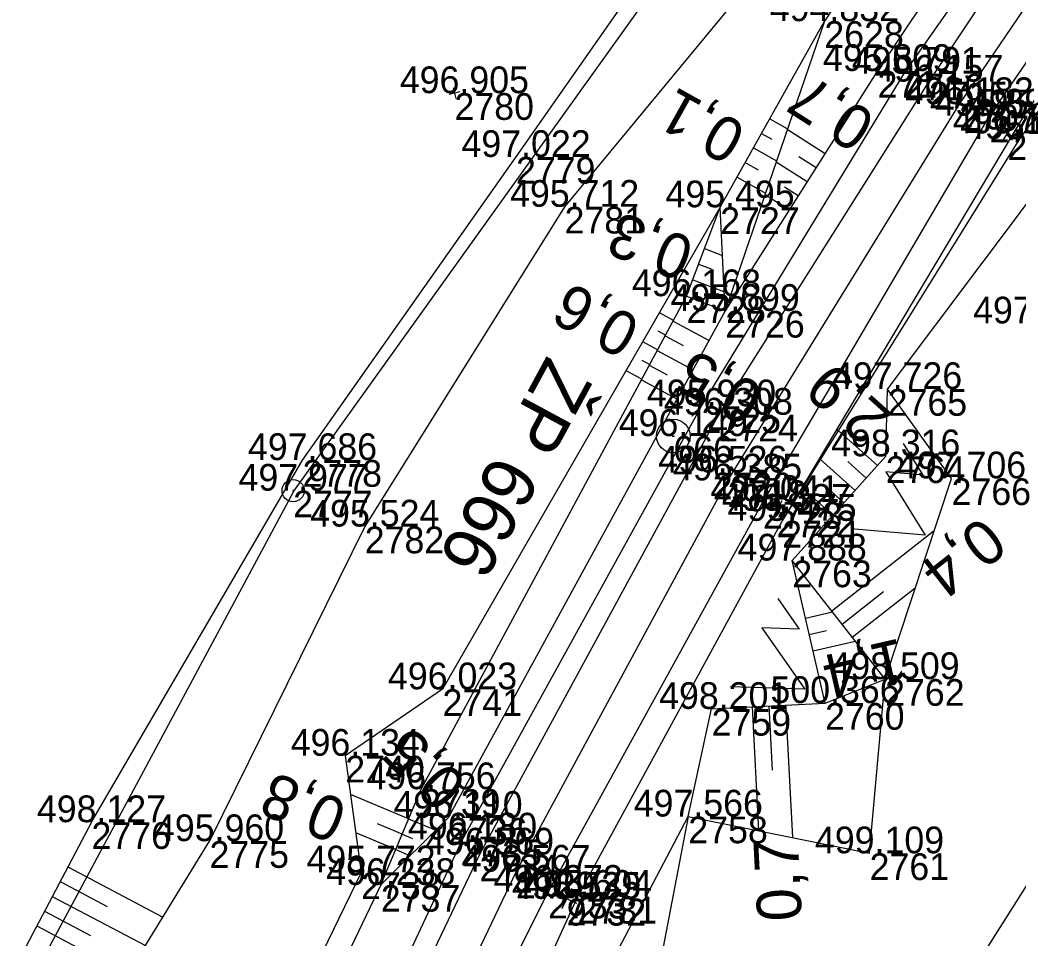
# Model space of a CAD drawing. Extents: x -1234191 to 23050, y -1290331 to -741191.
# Drawn here: x -864868.02 to -864823.18, y -1103072.61 to -1103031.37 of the extents above; entities that cross this region are included whole.
import ezdxf

# ---------------------------------------------------------------- set-up
doc = ezdxf.new("R2010")
doc.units = 0
for name, color, linetype in [('Vrstva 1', 7, 'Continuous'), ('Vrstva 4', 7, 'Continuous'), ('Vrstva 48', 7, 'Continuous'), ('Vrstva 49', 7, 'Continuous'), ('Vrstva 50', 7, 'Continuous'), ('Vrstva 53', 7, 'Continuous'), ('Vrstva 60', 7, 'Continuous'), ('Vrstva 61', 7, 'Continuous'), ('Vrstva 63', 7, 'Continuous'), ('Vrstva 7', 7, 'Continuous')]:
    doc.layers.add(name, color=color, linetype=linetype)

msp = doc.modelspace()

# ---------------------------------------------------------------- linework, layer by layer
at = {"layer": 'Vrstva 1'}
msp.add_lwpolyline([(-864787.36, -1102983.609), (-864800.066, -1102999.573), (-864808.926, -1103011.127), (-864817.494, -1103022.893), (-864825.83, -1103035.148), (-864836.227, -1103052.052), (-864845.733, -1103069.628), (-864853.5, -1103085.902), (-864861.945, -1103106.356), (-864868.475, -1103125.08), (-864874.102, -1103144.427), (-864878.675, -1103163.914), (-864882.14, -1103183.501), (-864883.755, -1103195.656), (-864884.979, -1103207.79), (-864886.147, -1103227.601), (-864886.275, -1103247.702), (-864885.251, -1103267.649), (-864883.95, -1103281.168), (-864883.144, -1103287.68), (-864880.026, -1103307.256), (-864876.201, -1103325.274)], dxfattribs=at)
at = {"layer": 'Vrstva 4'}
for points in [[(-864855.92, -1103084.82), (-864848.135, -1103068.183), (-864837.4, -1103048.723), (-864828.294, -1103033.779), (-864819.737, -1103021.567)], [(-864819.071, -1103021.913), (-864827.188, -1103034.138), (-864836.641, -1103049.101), (-864847.372, -1103068.859), (-864855.216, -1103085.296)], [(-864816.381, -1103023.935), (-864824.465, -1103035.662), (-864834.642, -1103053.018), (-864844.293, -1103070.531), (-864852.293, -1103086.512)], [(-864815.579, -1103024.784), (-864822.94, -1103035.693), (-864833.777, -1103053.868)], [(-864833.777, -1103053.868), (-864842.968, -1103070.758), (-864850.48, -1103087.221)]]:
    msp.add_lwpolyline(points, dxfattribs=at)
at = {"layer": 'Vrstva 48'}
for p, q in [((-864834.337, -1103035.808), (-864833.535, -1103036.256)), ((-864834.703, -1103036.462), (-864834.242, -1103036.72)), ((-864831.849, -1103037.375), (-864833.549, -1103036.296)), ((-864835.069, -1103037.117), (-864834.028, -1103037.699)), ((-864835.435, -1103037.771), (-864834.855, -1103038.096)), ((-864832.653, -1103038.641), (-864834.048, -1103037.756)), ((-864832.251, -1103038.008), (-864833.025, -1103037.517)), ((-864835.802, -1103038.426), (-864834.522, -1103039.142)), ((-864833.457, -1103039.908), (-864834.547, -1103039.216)), ((-864833.055, -1103039.274), (-864833.676, -1103038.88)), ((-864837.265, -1103041.638), (-864836.455, -1103041.945)), ((-864837.531, -1103042.339), (-864836.973, -1103042.551)), ((-864837.797, -1103043.04), (-864836.374, -1103043.58)), ((-864838.663, -1103044.866), (-864839.293, -1103044.527)), ((-864838.679, -1103044.897), (-864837.06, -1103045.768)), ((-864839.018, -1103045.526), (-864839.343, -1103045.352)), ((-864839.374, -1103046.187), (-864840.042, -1103045.827)), ((-864839.035, -1103045.557), (-864838.227, -1103045.992)), ((-864839.39, -1103046.218), (-864837.78, -1103047.085)), ((-864839.729, -1103046.847), (-864840.073, -1103046.662)), ((-864840.085, -1103047.508), (-864840.791, -1103047.127)), ((-864839.746, -1103046.878), (-864838.943, -1103047.31)), ((-864840.101, -1103047.538), (-864838.499, -1103048.401)), ((-864831.332, -1103049.768), (-864831.257, -1103049.813)), ((-864829.5, -1103051.388), (-864831.257, -1103049.813)), ((-864831.716, -1103050.412), (-864831.685, -1103050.431)), ((-864832.1, -1103051.056), (-864832.049, -1103051.087)), ((-864830.502, -1103052.505), (-864832.061, -1103051.107)), ((-864830.001, -1103051.946), (-864830.83, -1103051.203)), ((-864832.485, -1103051.7), (-864832.465, -1103051.712)), ((-864832.869, -1103052.345), (-864832.841, -1103052.361)), ((-864831.503, -1103053.621), (-864832.865, -1103052.4)), ((-864831.002, -1103053.063), (-864831.733, -1103052.408)), ((-864831.551, -1103057.914), (-864826.945, -1103054.307)), ((-864831.088, -1103058.505), (-864829.229, -1103057.049)), ((-864830.626, -1103059.095), (-864827.796, -1103056.879)), ((-864832.727, -1103058.242), (-864831.512, -1103057.963)), ((-864832.559, -1103058.973), (-864831.78, -1103058.794)), ((-864832.391, -1103059.704), (-864830.491, -1103059.267)), ((-864835.127, -1103062.223), (-864834.838, -1103067.791)), ((-864834.378, -1103062.184), (-864834.229, -1103065.065)), ((-864833.629, -1103062.146), (-864833.32, -1103068.099)), ((-864850.556, -1103067.255), (-864853.167, -1103066.158)), ((-864850.847, -1103067.946), (-864851.949, -1103067.483)), ((-864850.556, -1103067.255), (-864849.34, -1103067.765)), ((-864851.137, -1103068.638), (-864852.934, -1103067.883)), ((-864850.847, -1103067.946), (-864850.38, -1103068.142)), ((-864851.137, -1103068.638), (-864850.487, -1103068.911)), ((-864865.862, -1103069.41), (-864861.592, -1103071.666)), ((-864866.213, -1103070.074), (-864864.099, -1103071.19)), ((-864866.563, -1103070.737), (-864862.378, -1103072.947)), ((-864866.913, -1103071.4), (-864864.842, -1103072.494)), ((-864867.263, -1103072.063), (-864863.164, -1103074.229))]:
    msp.add_line(p, q, dxfattribs=at)
at = {"layer": 'Vrstva 49'}
for p, q in [((-864848.253, -1103034.598), (-864848.739, -1103034.714)), ((-864848.554, -1103034.413), (-864848.438, -1103034.899))]:
    msp.add_line(p, q, dxfattribs=at)
for points in [[(-864864.803, -1103067.405), (-864855.322, -1103051.138), (-864845.733, -1103037.523), (-864837.273, -1103025.418), (-864823.376, -1103006.596), (-864814.148, -1102994.673), (-864803.644, -1102992.309)], [(-864803.644, -1102992.309), (-864809.056, -1102996.882), (-864818.261, -1103010.716), (-864831.882, -1103031.421)], [(-864809.056, -1102996.882), (-864811.483, -1102996.245), (-864820.166, -1103008.494), (-864834.793, -1103029.157), (-864843.552, -1103039.76), (-864852.527, -1103054.125)], [(-864806.279, -1103012.707), (-864815.579, -1103024.784), (-864822.94, -1103035.693), (-864833.777, -1103053.868)], [(-864805.429, -1103013.211), (-864814.601, -1103024.977), (-864823.116, -1103036.714), (-864833.777, -1103053.868)], [(-864821.024, -1103020.98), (-864829.491, -1103033.659)], [(-864836.332, -1103044.437), (-864836.561, -1103039.783), (-864831.882, -1103031.421)], [(-864831.882, -1103031.421), (-864836.332, -1103044.437)], [(-864829.491, -1103033.659), (-864836.332, -1103044.437)], [(-864836.946, -1103062.318), (-864831.851, -1103062.053), (-864833.323, -1103055.651), (-864829.124, -1103050.968), (-864829.039, -1103047.948), (-864820.401, -1103036.45)], [(-864836.561, -1103039.783), (-864849.033, -1103061.436), (-864853.401, -1103064.421), (-864852.694, -1103069.662), (-864859.407, -1103083.519)], [(-864851.805, -1103070.227), (-864849.997, -1103065.923), (-864838.076, -1103043.776), (-864836.561, -1103039.783)], [(-864838.076, -1103043.776), (-864836.332, -1103044.437)], [(-864836.332, -1103044.437), (-864848.786, -1103067.212), (-864851.805, -1103070.227)], [(-864829.153, -1103060.976), (-864826.167, -1103051.959), (-864829.039, -1103047.948)], [(-864811.071, -1103051.708), (-864834.967, -1103089.456)], [(-864833.777, -1103053.868), (-864842.968, -1103070.758), (-864850.48, -1103087.221)], [(-864852.527, -1103054.125), (-864859.5, -1103068.257)], [(-864831.851, -1103062.053), (-864829.153, -1103060.976), (-864833.323, -1103055.651)], [(-864837.993, -1103067.151), (-864829.85, -1103068.803), (-864829.153, -1103060.976)], [(-864848.041, -1103086.285), (-864837.993, -1103067.151), (-864836.946, -1103062.318)], [(-864864.803, -1103067.405), (-864871.589, -1103080.252), (-864877.953, -1103100.004), (-864884.278, -1103123.532), (-864887.37, -1103144.597)], [(-864837.993, -1103067.151), (-864842.054, -1103088.354), (-864834.967, -1103089.456)], [(-864881.577, -1103125.033), (-864874.894, -1103104.785), (-864868.756, -1103083.343), (-864859.5, -1103068.257)], [(-864851.805, -1103070.227), (-864858.462, -1103084.152)]]:
    msp.add_lwpolyline(points, dxfattribs=at)
at = {"layer": 'Vrstva 50'}
for points in [[(-864828.338, -1103050.391), (-864827.453, -1103051.816), (-864829.124, -1103051.669), (-864827.355, -1103054.518), (-864830.696, -1103054.224)], [(-864833.977, -1103057.363), (-864833.015, -1103058.736), (-864834.691, -1103058.682), (-864832.766, -1103061.429), (-864836.118, -1103061.321)]]:
    msp.add_lwpolyline(points, dxfattribs=at)
at = {"layer": 'Vrstva 53'}
msp.add_line((-864855.72, -1103052.469), (-864855.768, -1103052.557), dxfattribs=at)
msp.add_lwpolyline([(-864889.03, -1103323.28), (-864892.77, -1103263.78), (-864892.91, -1103184.37), (-864883.42, -1103119.48), (-864874.29, -1103087.16), (-864855.71, -1103052.53), (-864814.57, -1102995.09), (-864799.32, -1102988.77), (-864779.65, -1102957.8), (-864778.43, -1102951.42), (-864757.64, -1102926.36), (-864755.77, -1102924.22), (-864753.95, -1102921.47), (-864728.77, -1102872.58), (-864694.07, -1102830.31)], dxfattribs=at)
msp.add_circle((-864855.744, -1103052.513), 0.499, dxfattribs=at)
at = {"layer": 'Vrstva 60'}
for p, q in [((-864831.882, -1103031.421), (-864831.882, -1103031.421)), ((-864829.491, -1103033.659), (-864829.491, -1103033.659)), ((-864828.294, -1103033.779), (-864828.294, -1103033.779)), ((-864827.188, -1103034.138), (-864827.188, -1103034.138)), ((-864848.496, -1103034.656), (-864848.496, -1103034.656)), ((-864825.83, -1103035.148), (-864825.83, -1103035.148)), ((-864824.465, -1103035.662), (-864824.465, -1103035.662)), ((-864823.661, -1103036.461), (-864823.661, -1103036.461)), ((-864845.733, -1103037.523), (-864845.733, -1103037.523)), ((-864843.552, -1103039.76), (-864843.552, -1103039.76)), ((-864836.561, -1103039.783), (-864836.561, -1103039.783)), ((-864838.076, -1103043.776), (-864838.076, -1103043.776)), ((-864836.332, -1103044.437), (-864836.332, -1103044.437)), ((-864829.039, -1103047.948), (-864829.039, -1103047.948)), ((-864837.4, -1103048.723), (-864837.4, -1103048.723)), ((-864836.641, -1103049.101), (-864836.641, -1103049.101)), ((-864838.665, -1103050.059), (-864838.665, -1103050.059)), ((-864855.322, -1103051.138), (-864855.322, -1103051.138)), ((-864829.124, -1103050.968), (-864829.124, -1103050.968)), ((-864836.895, -1103051.7), (-864836.895, -1103051.7)), ((-864836.227, -1103052.052), (-864836.227, -1103052.052)), ((-864826.167, -1103051.959), (-864826.167, -1103051.959)), ((-864855.744, -1103052.513), (-864855.744, -1103052.513)), ((-864834.642, -1103053.018), (-864834.642, -1103053.018)), ((-864834.035, -1103053.414), (-864834.035, -1103053.414)), ((-864833.777, -1103053.868), (-864833.777, -1103053.868)), ((-864852.527, -1103054.125), (-864852.527, -1103054.125)), ((-864833.323, -1103055.651), (-864833.323, -1103055.651)), ((-864829.153, -1103060.976), (-864829.153, -1103060.976)), ((-864849.033, -1103061.436), (-864849.033, -1103061.436)), ((-864831.851, -1103062.053), (-864831.851, -1103062.053)), ((-864836.946, -1103062.318), (-864836.946, -1103062.318)), ((-864853.401, -1103064.421), (-864853.401, -1103064.421)), ((-864849.997, -1103065.923), (-864849.997, -1103065.923)), ((-864864.803, -1103067.405), (-864864.803, -1103067.405)), ((-864848.786, -1103067.212), (-864848.786, -1103067.212)), ((-864837.993, -1103067.151), (-864837.993, -1103067.151)), ((-864859.5, -1103068.257), (-864859.5, -1103068.257)), ((-864848.135, -1103068.183), (-864848.135, -1103068.183)), ((-864829.85, -1103068.803), (-864829.85, -1103068.803)), ((-864847.372, -1103068.859), (-864847.372, -1103068.859)), ((-864852.694, -1103069.662), (-864852.694, -1103069.662)), ((-864845.733, -1103069.628), (-864845.733, -1103069.628)), ((-864851.805, -1103070.227), (-864851.805, -1103070.227)), ((-864844.293, -1103070.531), (-864844.293, -1103070.531)), ((-864843.46, -1103070.843), (-864843.46, -1103070.843)), ((-864843.454, -1103070.85), (-864843.454, -1103070.85)), ((-864842.968, -1103070.758), (-864842.968, -1103070.758))]:
    msp.add_line(p, q, dxfattribs=at)
at = {"layer": 'Vrstva 63'}
msp.add_line((-864838.715, -1103050.059), (-864838.615, -1103050.059), dxfattribs=at)
msp.add_circle((-864838.665, -1103050.059), 0.756, dxfattribs=at)
at = {"layer": 'Vrstva 7'}
for p, q in [((-864823.38, -1103036.048), (-864823.942, -1103036.874)), ((-864823.248, -1103036.742), (-864824.074, -1103036.18)), ((-864833.797, -1103052.974), (-864834.273, -1103053.854)), ((-864833.595, -1103053.652), (-864834.475, -1103053.176)), ((-864843.009, -1103071.058), (-864843.911, -1103070.628)), ((-864843.245, -1103070.392), (-864843.675, -1103071.294)), ((-864843.239, -1103070.399), (-864843.669, -1103071.301)), ((-864843.003, -1103071.065), (-864843.905, -1103070.635))]:
    msp.add_line(p, q, dxfattribs=at)

# ---------------------------------------------------------------- texts
at = {"layer": 'Vrstva 48'}
for s, rotation, p in [('0,7', 147.5959, (-864829.476, -1103035.703)), ('0,1', 150.7706, (-864835.283, -1103036.182)), ('0,3', 159.2226, (-864837.615, -1103041.268)), ('0,6', 151.7079, (-864840.037, -1103044.874)), ('0,5', 151.3289, (-864834.49, -1103047.908)), ('2,9', 138.1191, (-864828.758, -1103049.123)), ('0,4', 218.0644, (-864824.771, -1103053.603)), ('1,4', 192.9489, (-864828.478, -1103059.133)), ('0,5', 134.962, (-864847.842, -1103065.644)), ('0,8', 157.214, (-864853.198, -1103066.554)), ('0,7', 92.9774, (-864832.885, -1103071.805))]:
    msp.add_text(s, height=2, rotation=rotation, dxfattribs=at).set_placement(p)
at = {"layer": 'Vrstva 60'}
for s, p in [('2628', (-864831.882, -1103032.621)), ('2717', (-864829.491, -1103034.859)), ('2716', (-864828.294, -1103034.979)), ('2715', (-864827.188, -1103035.338)), ('2780', (-864848.496, -1103035.856)), ('2707', (-864825.83, -1103036.348)), ('2714', (-864824.465, -1103036.862)), ('2713', (-864823.661, -1103037.661)), ('2779', (-864845.733, -1103038.723)), ('2781', (-864843.552, -1103040.96)), ('2727', (-864836.561, -1103040.983)), ('2728', (-864838.076, -1103044.976)), ('2726', (-864836.332, -1103045.637)), ('2765', (-864829.039, -1103049.148)), ('2725', (-864837.4, -1103049.923)), ('2724', (-864836.641, -1103050.301)), ('666', (-864838.665, -1103051.259)), ('2778', (-864855.322, -1103052.338)), ('2764', (-864829.124, -1103052.168)), ('2720', (-864836.895, -1103052.9)), ('2718', (-864836.227, -1103053.252)), ('2766', (-864826.167, -1103053.159)), ('2777', (-864855.744, -1103053.713)), ('2723', (-864834.642, -1103054.218)), ('2722', (-864834.035, -1103054.614)), ('2721', (-864833.777, -1103055.068)), ('2782', (-864852.527, -1103055.325)), ('2763', (-864833.323, -1103056.851)), ('2762', (-864829.153, -1103062.176)), ('2741', (-864849.033, -1103062.636)), ('2760', (-864831.851, -1103063.253)), ('2759', (-864836.946, -1103063.518)), ('2740', (-864853.401, -1103065.621)), ('2739', (-864849.997, -1103067.123)), ('2776', (-864864.803, -1103068.605)), ('2736', (-864848.786, -1103068.412)), ('2758', (-864837.993, -1103068.351)), ('2775', (-864859.5, -1103069.457)), ('2735', (-864848.135, -1103069.383)), ('2761', (-864829.85, -1103070.003)), ('2734', (-864847.372, -1103070.059)), ('2738', (-864852.694, -1103070.862)), ('2729', (-864845.733, -1103070.828)), ('2737', (-864851.805, -1103071.427)), ('2733', (-864844.293, -1103071.731)), ('2732', (-864843.46, -1103072.043)), ('9732', (-864843.454, -1103072.05)), ('2731', (-864842.968, -1103071.958))]:
    msp.add_text(s, height=1.2, dxfattribs=at).set_placement(p)
at = {"layer": 'Vrstva 61'}
for s, p in [('494.832', (-864834.33, -1103031.421)), ('495.809', (-864831.945, -1103033.659)), ('495.791', (-864830.651, -1103033.779)), ('496.157', (-864829.64, -1103034.138)), ('496.905', (-864850.952, -1103034.656)), ('496.182', (-864828.278, -1103035.148)), ('495.892', (-864826.913, -1103035.662)), ('495.263', (-864825.392, -1103035.693)), ('496.112', (-864826.109, -1103036.461)), ('495.090', (-864825.567, -1103036.714)), ('497.022', (-864848.181, -1103037.523)), ('495.712', (-864846, -1103039.76)), ('495.495', (-864839.017, -1103039.783)), ('496.168', (-864840.53, -1103043.776)), ('495.699', (-864838.786, -1103044.437)), ('497.150', (-864825.199, -1103045)), ('497.726', (-864831.491, -1103047.948)), ('495.930', (-864839.851, -1103048.723)), ('496.308', (-864839.095, -1103049.101)), ('496.149', (-864841.119, -1103050.059)), ('497.686', (-864857.774, -1103051.138)), ('498.316', (-864831.576, -1103050.968)), ('496.526', (-864839.347, -1103051.7)), ('496.385', (-864838.683, -1103052.052)), ('497.706', (-864828.619, -1103051.959)), ('497.977', (-864858.196, -1103052.513)), ('496.041', (-864836.999, -1103053.018)), ('496.327', (-864836.487, -1103053.414)), ('495.475', (-864836.233, -1103053.868)), ('495.524', (-864854.978, -1103054.125)), ('497.888', (-864835.777, -1103055.651)), ('498.509', (-864831.607, -1103060.976)), ('496.023', (-864851.485, -1103061.436)), ('498.201', (-864839.303, -1103062.318)), ('500.366', (-864834.303, -1103062.053)), ('496.134', (-864855.852, -1103064.421)), ('496.756', (-864852.449, -1103065.923)), ('496.110', (-864851.237, -1103067.212)), ('497.566', (-864840.445, -1103067.151)), ('498.127', (-864867.255, -1103067.405)), ('495.960', (-864861.951, -1103068.257)), ('496.180', (-864850.586, -1103068.183)), ('496.569', (-864849.826, -1103068.859)), ('499.109', (-864832.304, -1103068.803)), ('495.772', (-864855.142, -1103069.662)), ('496.567', (-864848.185, -1103069.628)), ('496.238', (-864854.259, -1103070.227)), ('496.272', (-864846.741, -1103070.531)), ('496.535', (-864845.916, -1103070.843)), ('496.539', (-864845.908, -1103070.85)), ('495.604', (-864845.419, -1103070.758))]:
    msp.add_text(s, height=1.2, dxfattribs=at).set_placement(p)
at = {"layer": 'Vrstva 63'}
msp.add_text('ŽP 666', height=2.4, rotation=241.5932, dxfattribs=at).set_placement((-864844.319, -1103046.391))

doc.saveas('drawing.dxf')
